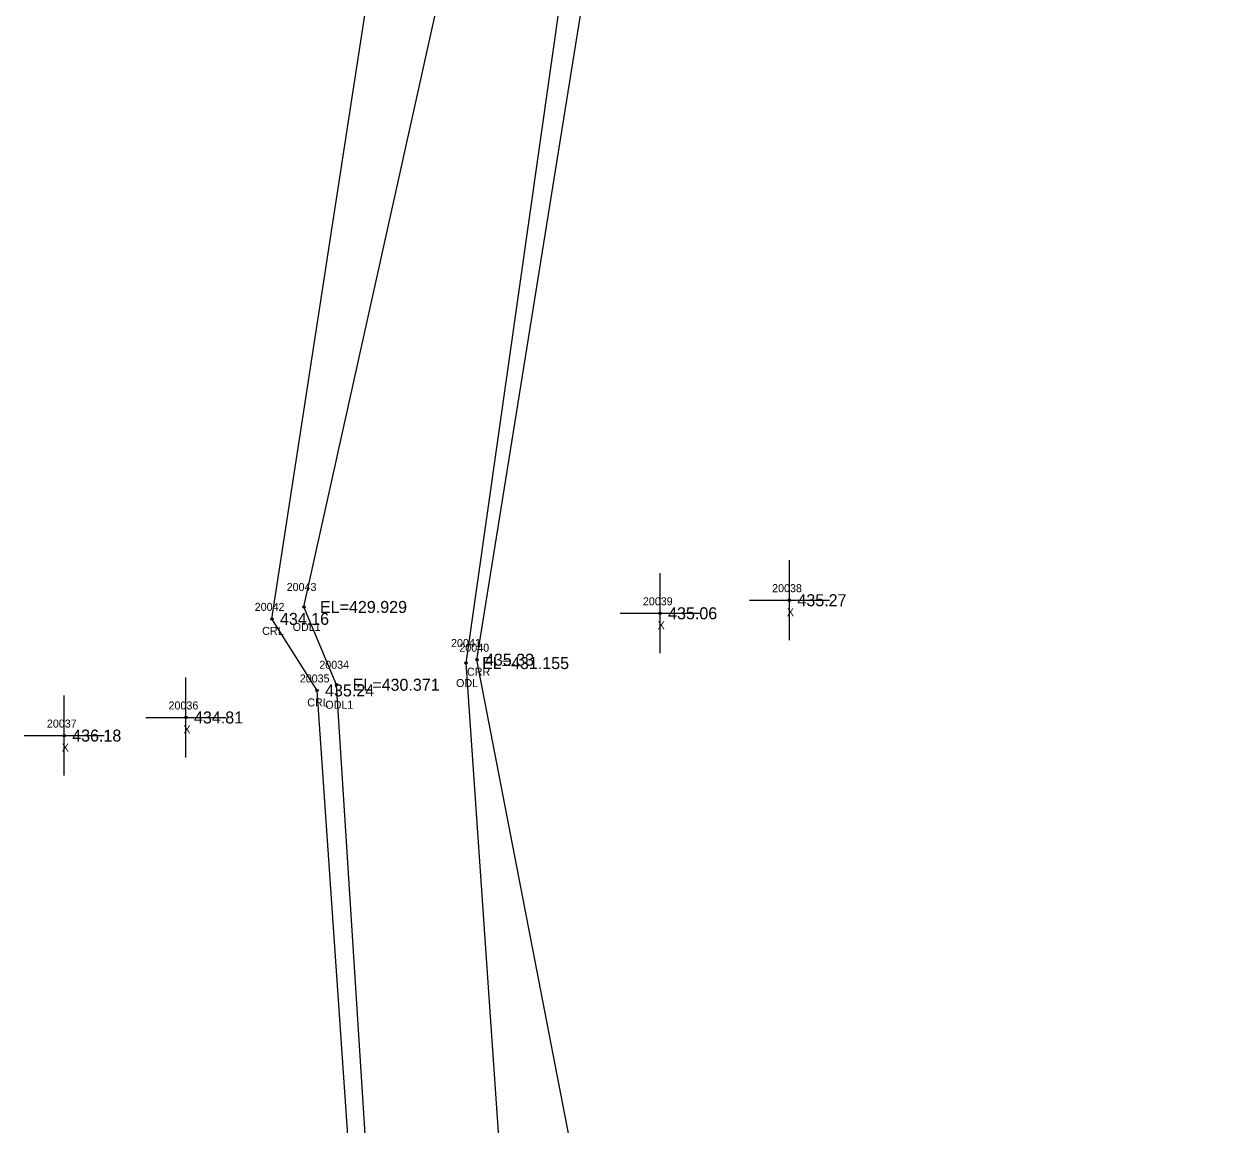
# Model space of a CAD drawing. Extents: x 1810114 to 1811498, y 790790 to 791824.
# Drawn here: x 1810681.5 to 1810832.5, y 791542.1 to 791679.6 of the extents above; entities that cross this region are included whole.
import ezdxf

# ---------------------------------------------------------------- set-up
doc = ezdxf.new("R2010")
doc.units = 0
for name, color, linetype in [('RD_EX_H2O', 7, 'Continuous'), ('RD_EX_H2O_txCode', 7, 'Continuous'), ('RD_EX_Misc', 7, 'Continuous'), ('RD_EX_Misc_txCode', 7, 'Continuous'), ('RD_EX_TX_H2O_ELEV', 7, 'Continuous'), ('RD_EX_TX_Misc_ELEV', 7, 'Continuous'), ('RD_SMD_Locator', 7, 'Continuous')]:
    doc.layers.add(name, color=color, linetype=linetype)

msp = doc.modelspace()

# ---------------------------------------------------------------- linework, layer by layer
at = {"layer": 'RD_EX_H2O'}
for points in [[(1810797.71, 791296.87), (1810832.51, 791426.19), (1810824.93, 791438.48), (1810774.65, 791454.91), (1810754.82, 791471.31), (1810756.82, 791503.13), (1810738.07, 791600.2), (1810752.73, 791691.4), (1810775.78, 791733), (1810786.04, 791774.85), (1810772.38, 791809.33)], [(1810794.5, 791298.9), (1810828.59, 791424.04), (1810821.51, 791432.91), (1810774.54, 791452.98), (1810741.95, 791465.37), (1810743.78, 791497), (1810736.7, 791599.78), (1810749.88, 791692.36), (1810769.68, 791736.66), (1810784.24, 791774.17), (1810766.9, 791808.95)], [(1810781.61, 791303.43), (1810807.2, 791415.78), (1810808.22, 791420.49), (1810765.69, 791434.41), (1810731.68, 791459.26), (1810725.69, 791486.37), (1810718.09, 791596.36), (1810712.45, 791605.3), (1810726.19, 791694.57), (1810745.89, 791743.36), (1810754.16, 791771.51), (1810757.05, 791789.67), (1810743.21, 791805.43)], [(1810783.58, 791301.54), (1810809.42, 791415.43), (1810809.03, 791421.06), (1810765.94, 791440.4), (1810731.85, 791461.34), (1810727.54, 791486.73), (1810720.53, 791597.07), (1810716.45, 791606.79), (1810735.63, 791693.4), (1810750.76, 791743.08), (1810758.52, 791771.58), (1810758.6, 791790.56), (1810750.48, 791805.79)]]:
    msp.add_lwpolyline(points, dxfattribs=at)
at = {"layer": 'RD_EX_Misc'}
for p, q in [((1810777.11, 791602.64), (1810777.11, 791612.64)), ((1810760.95, 791601), (1810760.95, 791611)), ((1810772.11, 791607.64), (1810782.11, 791607.64)), ((1810755.95, 791606), (1810765.95, 791606)), ((1810701.71, 791587.98), (1810701.71, 791597.98)), ((1810686.49, 791585.72), (1810686.49, 791595.72)), ((1810696.71, 791592.98), (1810706.71, 791592.98)), ((1810681.49, 791590.72), (1810691.49, 791590.72))]:
    msp.add_line(p, q, dxfattribs=at)
at = {"layer": 'RD_SMD_Locator'}
for centre in [(1810716.45, 791606.79), (1810777.11, 791607.64), (1810712.45, 791605.3), (1810760.95, 791606), (1810736.7, 791599.78), (1810738.07, 791600.2), (1810718.09, 791596.36), (1810720.53, 791597.07), (1810701.71, 791592.98), (1810686.49, 791590.72)]:
    msp.add_circle(centre, 0.15, dxfattribs=at)

# ---------------------------------------------------------------- texts
at = {"layer": 'RD_EX_H2O_txCode'}
for s, p in [('20043', (1810714.29, 791608.79)), ('20042', (1810710.3, 791606.3)), ('CRL', (1810711.23, 791603.3)), ('ODL1', (1810715.04, 791603.79)), ('20041', (1810734.83, 791601.78)), ('20040', (1810735.87, 791601.2)), ('20034', (1810718.37, 791599.07)), ('CRR', (1810736.82, 791598.2)), ('20035', (1810715.93, 791597.36)), ('ODL', (1810735.46, 791596.78)), ('CRL', (1810716.86, 791594.36)), ('ODL1', (1810719.12, 791594.07))]:
    msp.add_text(s, height=1, dxfattribs=at).set_placement(p)
at = {"layer": 'RD_EX_Misc_txCode'}
for s, p in [('20038', (1810774.95, 791608.64)), ('20039', (1810758.8, 791607)), ('X', (1810776.79, 791605.64)), ('X', (1810760.64, 791604)), ('20036', (1810699.53, 791593.98)), ('20037', (1810684.33, 791591.72)), ('X', (1810701.39, 791590.98)), ('X', (1810686.18, 791588.72))]:
    msp.add_text(s, height=1, dxfattribs=at).set_placement(p)
at = {"layer": 'RD_EX_TX_H2O_ELEV'}
for s, p in [('EL=429.929', (1810718.45, 791606.04)), ('434.16', (1810713.45, 791604.55)), ('435.33', (1810739.07, 791599.45)), ('EL=431.155', (1810738.7, 791599.03)), ('EL=430.371', (1810722.53, 791596.32)), ('435.24', (1810719.09, 791595.61))]:
    msp.add_text(s, height=1.5, dxfattribs=at).set_placement(p)
at = {"layer": 'RD_EX_TX_Misc_ELEV'}
for s, p in [('435.27', (1810778.11, 791606.89)), ('435.06', (1810761.95, 791605.25)), ('434.81', (1810702.71, 791592.23)), ('436.18', (1810687.49, 791589.97))]:
    msp.add_text(s, height=1.5, dxfattribs=at).set_placement(p)

doc.saveas('drawing.dxf')
